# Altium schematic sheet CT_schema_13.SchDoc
size 388 x 278 mm
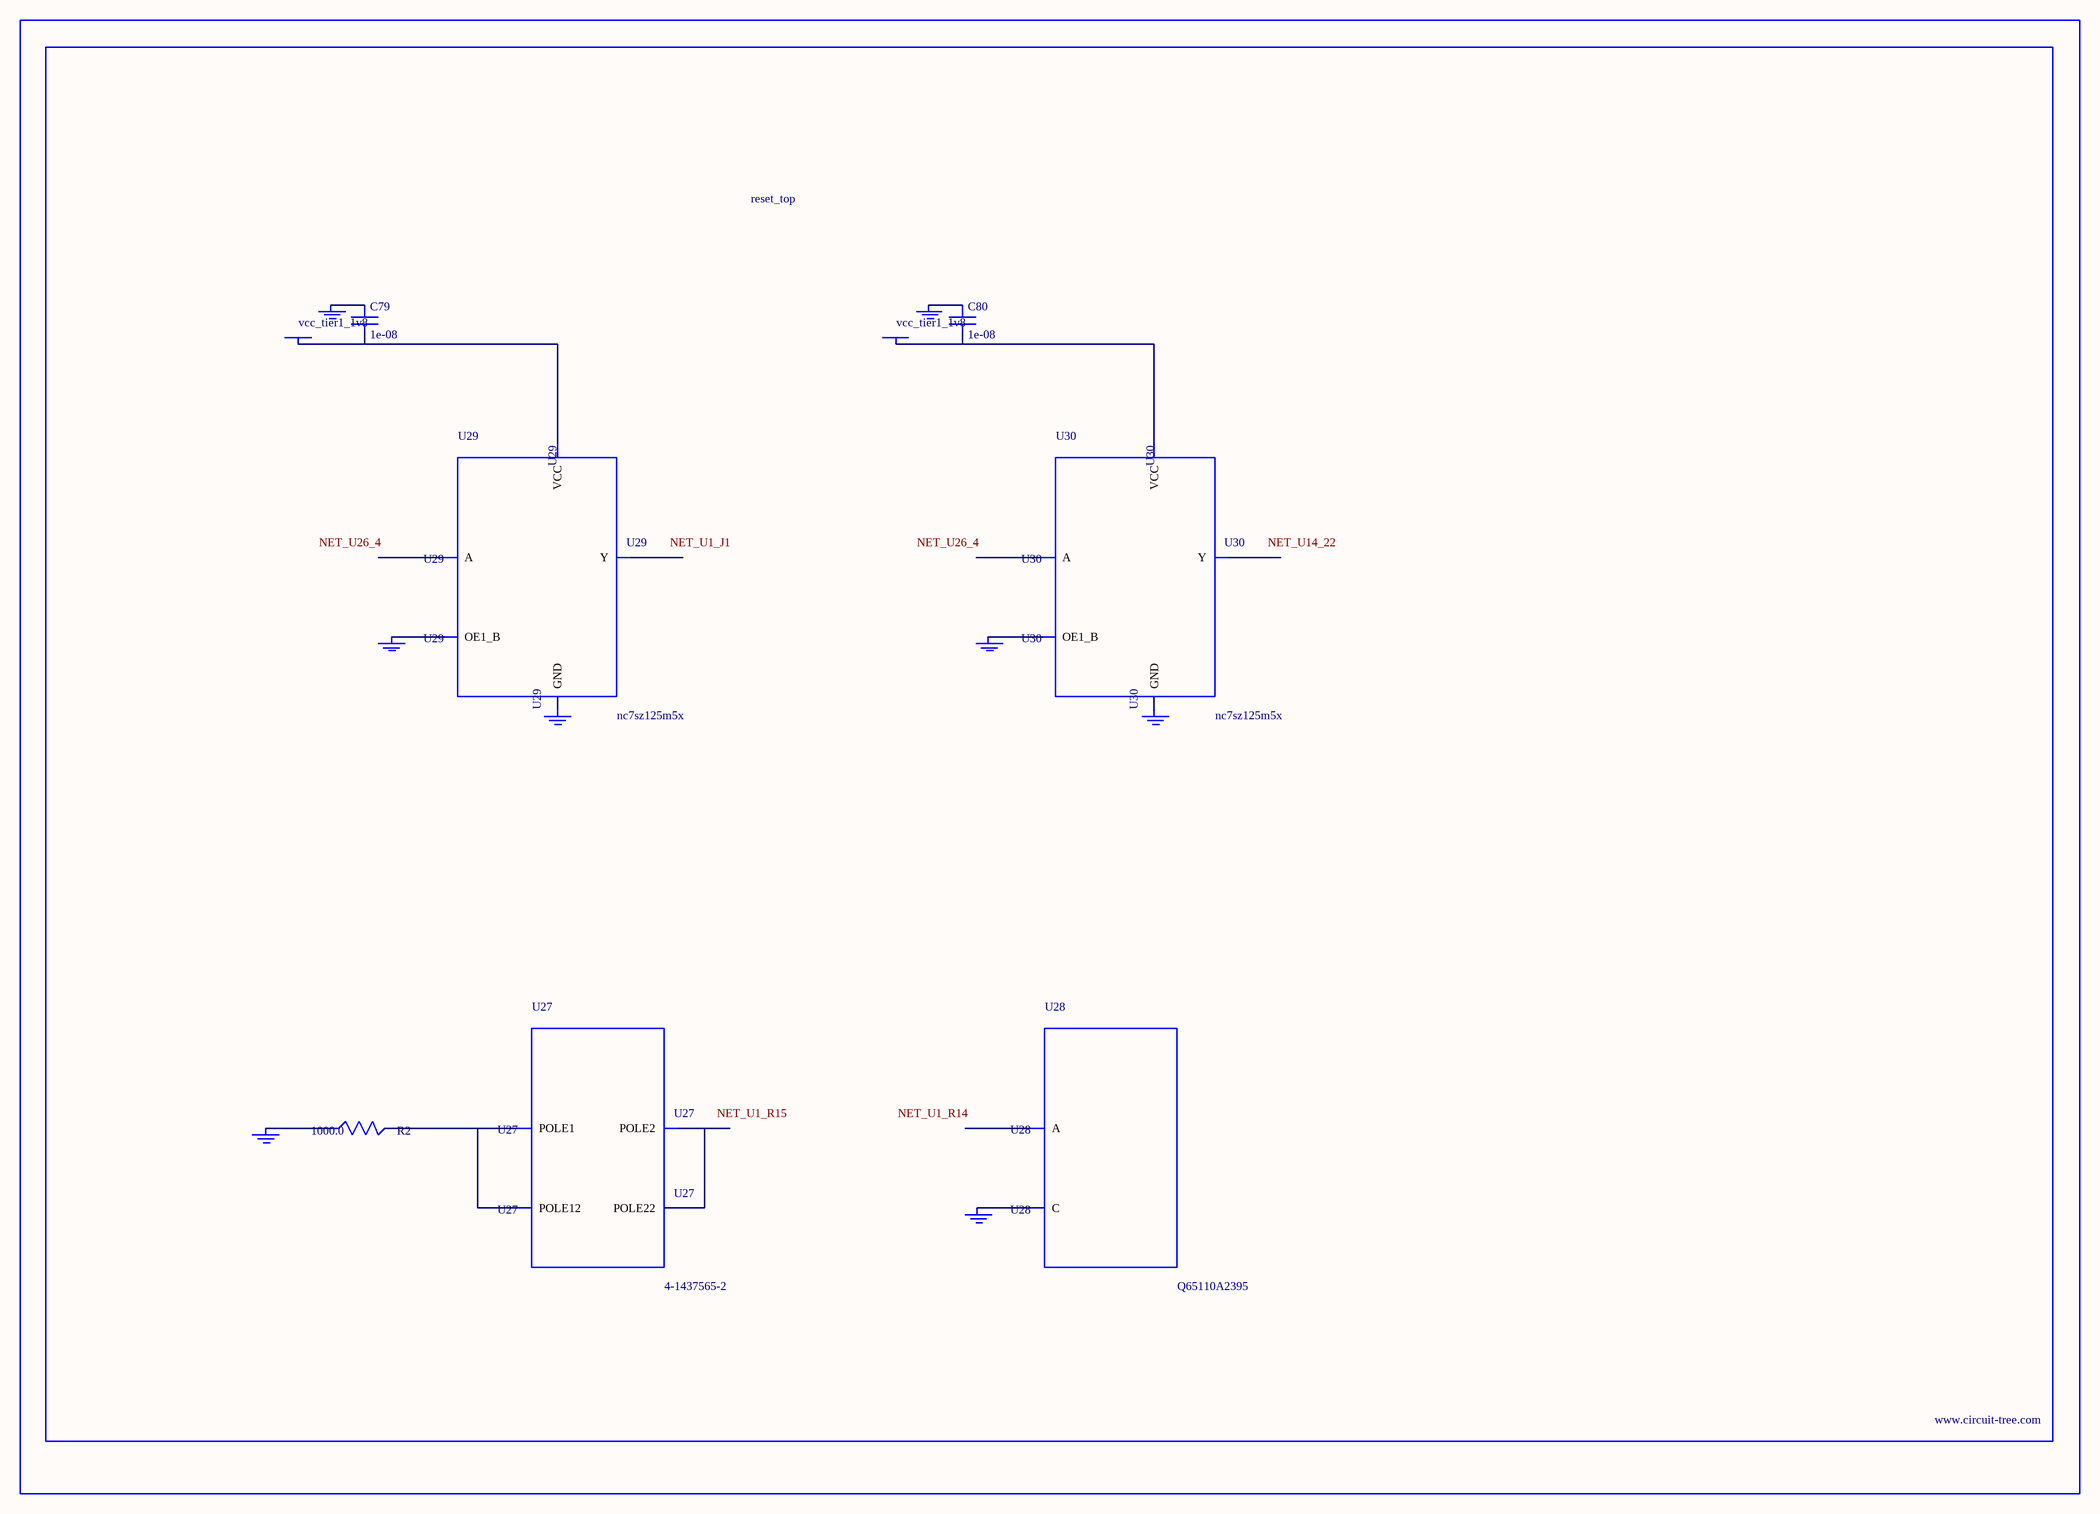
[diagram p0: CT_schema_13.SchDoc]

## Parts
BORDER12  (no value)
C79  1e-08  [C0402]
C80  1e-08  [C0402]
GND_INSTANCE_12_0  (no value)
GND_INSTANCE_12_1  (no value)
GND_INSTANCE_12_2  (no value)
GND_INSTANCE_12_3  (no value)
GND_INSTANCE_12_4  (no value)
GND_INSTANCE_12_5  (no value)
GND_INSTANCE_12_6  (no value)
GND_INSTANCE_12_7  (no value)
POWER_INSTANCE_12_0  vcc_tier1_1v8
POWER_INSTANCE_12_1  vcc_tier1_1v8
R2  1000.0  [R0603]
U27  4-1437565-2  [SW_4-1437565-2]
U28  Q65110A2395  [LGM67K-G1J2-24-Z]
U29  nc7sz125m5x  [NC7SZ125M5X]
U30  nc7sz125m5x  [NC7SZ125M5X]

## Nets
NetC79_1: C79.1 GND_INSTANCE_12_2.0(GND)
NetC79_2: C79.2 POWER_INSTANCE_12_0.0(PWR) U29.5(VCC)
NetC80_1: C80.1 GND_INSTANCE_12_5.0(GND)
NetC80_2: C80.2 POWER_INSTANCE_12_1.0(PWR) U30.5(VCC)
NetGND_INSTANCE_12_0_0: GND_INSTANCE_12_0.0(GND) R2.1
NetGND_INSTANCE_12_1_0: GND_INSTANCE_12_1.0(GND) U28.C
NetGND_INSTANCE_12_3_0: GND_INSTANCE_12_3.0(GND) U29.1(OE1_B)
NetGND_INSTANCE_12_4_0: GND_INSTANCE_12_4.0(GND) U29.3(GND)
NetGND_INSTANCE_12_6_0: GND_INSTANCE_12_6.0(GND) U30.1(OE1_B)
NetGND_INSTANCE_12_7_0: GND_INSTANCE_12_7.0(GND) U30.3(GND)
NetR2_2: R2.2 U27.1(POLE1) U27.2(POLE12)
NetU27_3: U27.3(POLE2) U27.4(POLE22)

Not connected (* = marked no-connect by the designer): U28 A; U29 2(A) 4(Y); U30 2(A) 4(Y)

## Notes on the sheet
- Labels drawn without touching a wire or pin: NET_U1_J1, NET_U1_R14, NET_U1_R15, NET_U14_22, NET_U26_4

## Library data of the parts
BORDER12 = BORDER_PAGE12
C79 C80 = C0402C103K3RAC
GND_INSTANCE_12_0-GND_INSTANCE_12_7 = GND
POWER_INSTANCE_12_0 POWER_INSTANCE_12_1 = PWR
R2 = RC0603JR-071KL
